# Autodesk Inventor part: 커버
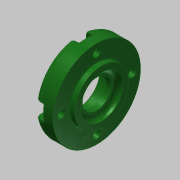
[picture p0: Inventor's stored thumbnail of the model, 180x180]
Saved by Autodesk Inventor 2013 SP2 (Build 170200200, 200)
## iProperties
Created: 2015-11
Part Number: 커버
Material: 알루미늄 6061
Document SubType Name: Modeling
Designer: mduedu
Density: 1 g/cm^3
Author: mduedu
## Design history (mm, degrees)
sketch "스케치1"
  geometry: L1 (-7, 0)-(7, 0); L2 (-7, 0)-(-7, 26); L3 (-7, 26)-(4, 26); L4 (4, 26)-(4, 16); L5 (4, 16)-(7, 16); L6 (7, 16)-(7, 0); 2 further points
  constraints: 12 end point, 3 perpendicular, 2 parallel, 1 coincident, 1 horizontal, 1 midpoint
  dimensions: "d0" = 14 distance of L1.start L1.end; "d1" = 52 diameter of L3 L1; "d2" = 3 distance of L4.end L5.end; "d3" = 32 diameter of L5 L1
revolve "회전1" sketch "스케치1" stored, may be unused: angle "d4" = 90 deg
hole "구멍1" diameter "d7" = 25; stored, may be unused: countersink angle "d11" = 90 deg, drill point angle "d13" = 0 deg; dims "d5" = 10, "d6" = 10, "d8" = 6, "d9" = 4, "d10" = 2, "d12" = 3
hole "구멍2" diameter "d16" = 25; stored, may be unused: countersink angle "d20" = 90 deg, drill point angle "d22" = 0 deg; dims "d17" = 6, "d18" = 4, "d19" = 2, "d21" = 7.7, "d58" = 10, "d59" = 10
hole "구멍3" diameter "d25" = 17; stored, may be unused: countersink angle "d29" = 90 deg, drill point angle "d31" = 0 deg; dims "d23" = 10, "d24" = 10, "d26" = 6, "d27" = 4, "d28" = 2, "d30" = 4.2
chamfer "모따기1" distance "d32" = 0.6; stored, may be unused: second distance "d33" = 2, angle "d34" = 30 deg
fillet "모깎기1" dims "d35" = 0.3
fillet "모깎기2" dims "d36" = 3
fillet "모깎기3" dims "d37" = 3
fillet "모깎기4" dims "d38" = 0.3
sketch "스케치3" dims "d61" = 42
  geometry: C1 r 26 at (0, 0) reference; 2 further points
  constraints: 2 vertical alignment, 1 coincident, 2 other
hole "구멍4" sketch "스케치3" at (0, -21) diameter "d44" = 4.5; stored, may be unused: countersink angle "d48" = 90 deg, drill point angle "d50" = 0 deg; dims "d45" = 6, "d46" = 8, "d47" = 4.6, "d49" = 8
sketch "스케치4"
  geometry: L1 (-4, 0)-(-4, -4.69); L2 (4, 0)-(4, -4.69); A1 r 4 centre (0, 0) between (3.614, -1.714) and (-3.614, -1.714) reference; A2 r 26 centre (0, 21) between (-4, -4.69) and (4, -4.69) reference; 1 further point
  constraints: 4 end point, 4 point on circle, 2 tangent, 1 parallel, 1 vertical
extrude "돌출1" cut sketch "스케치4" stored distance "d51" = 0; taper "d52" = 0 deg
fillet "모깎기5" dims "d56" = 0.3
fillet "모깎기6" dims "d57" = 1
node "솔리드1"
pattern_circular "원형 패턴1" dims angle "d54" = 360 deg
